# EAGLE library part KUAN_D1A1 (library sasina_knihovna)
Rele s jednim spinacim dotekem.
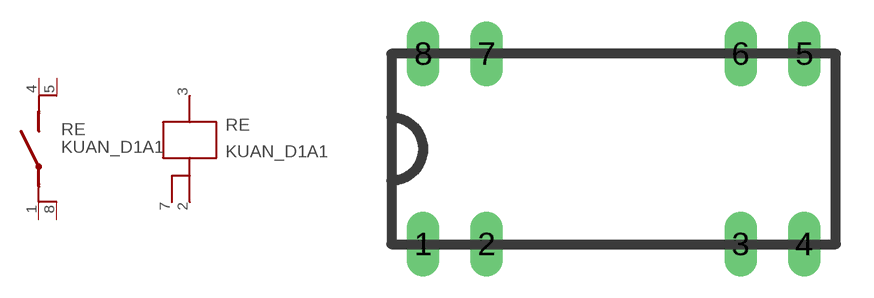
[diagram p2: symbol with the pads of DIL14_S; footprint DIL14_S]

Designator prefix RE; gates G$1=CIVKA G$2=DOTEK_SPINACI

## KUAN_D1A1  [DIL14_S]
1  G$2:P  pas
2  G$1:C1  pas
3  G$1:C2  pas
4  G$2:S  pas
5  G$2:S1  pas
7  G$1:C1_A  pas
8  G$2:P1  pas

## Footprint DIL14_S (pad centres in mm)
drill 0.8 long: 1 0,-1.27; 2 2.54,-1.27; 3 12.7,-1.27; 4 15.24,-1.27; 5 15.24,6.35; 6 12.7,6.35; 7 2.54,6.35; 8 0,6.35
